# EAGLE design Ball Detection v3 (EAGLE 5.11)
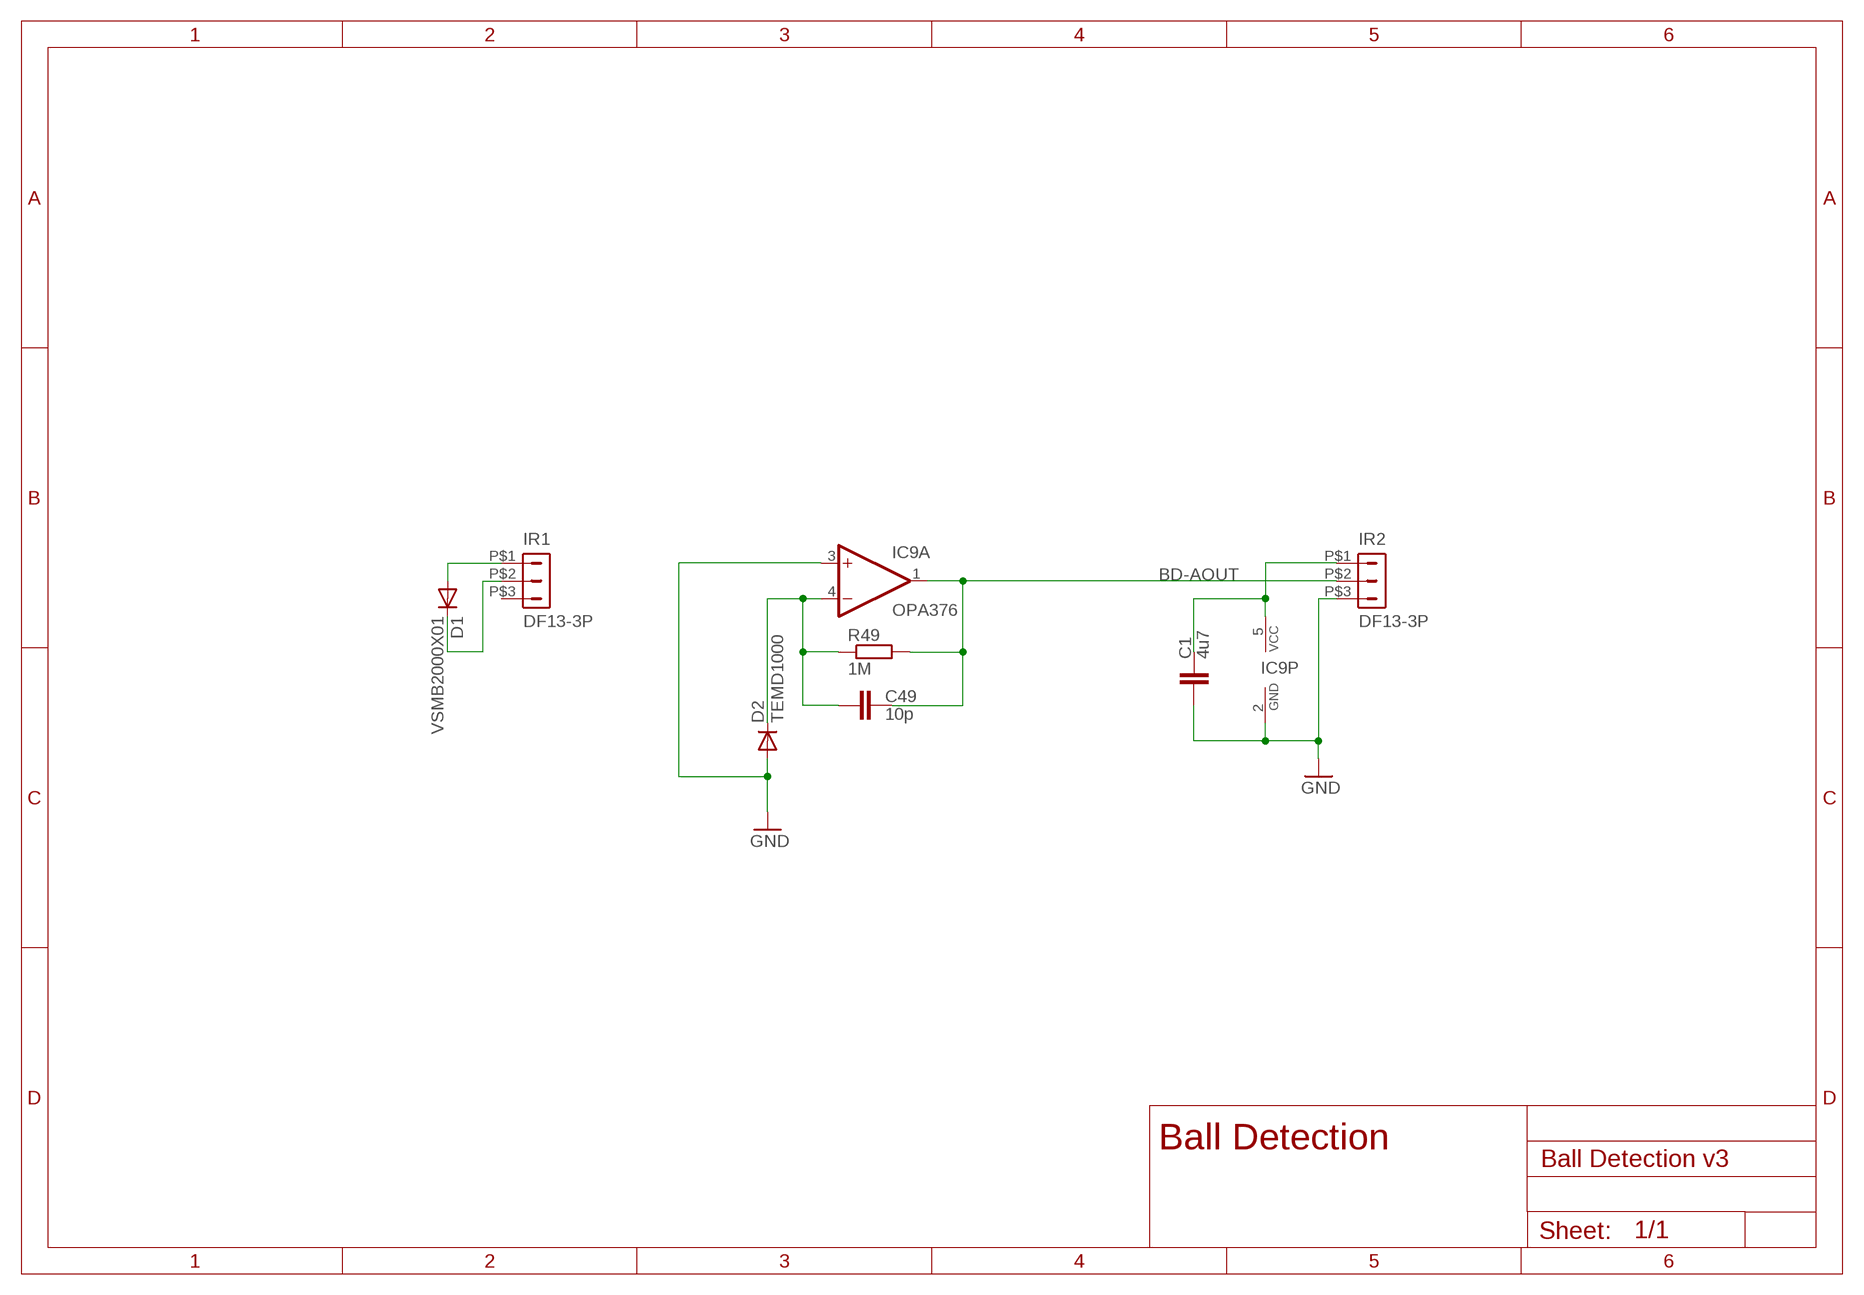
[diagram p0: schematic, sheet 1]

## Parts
C1  4u7  C-EUC0603  [C0603]
C49  10p  C-EUC0603  [C0603]
D1  VSMB2000X01  DIODE  [LED-GULLR]
D2  TEMD1000  DIODE  [LED-GULLR]
IC9  OPA376  AD-OP1RT  [SOT23-5]
IR1  DF13-3P  DF13-3P-1.25H  [DF13A-3P-1.25H]
IR2  DF13-3P  DF13-3P-1.25H  [DF13A-3P-1.25H]
R49  1M  R-EU_R0603  [R0603]

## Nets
BD-AOUT: C49.2 IC9.1(A:OUT) IR2.P$2 R49.2
GND: C1.1 D2.A IC9.2(P:GND) IC9.3(A:+IN) IR2.P$3
N$1: C1.2 IC9.5(P:VCC) IR2.P$1
N$114: C49.1 D2.C IC9.4(A:-IN) R49.1
N$182: D1.C IR1.P$2
VDD1: D1.A IR1.P$1
Unconnected: IR1.P$3

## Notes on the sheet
- Ball Detection

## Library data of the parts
C1 C49 = rcl:C-EU: CAPACITOR, European symbol
D1 D2 = Marvin:DIODE
IC9 = Marvin:AD-OP1
IR1 IR2 = con-hirose-df13:DF13-3P-1.25: DF13-3P 1.25mm Pitch Miniature Crimping Connector.
R49 = rcl:R-EU_: RESISTOR, European symbol

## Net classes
0 default: width 0.152 mm, clearance 0.152 mm

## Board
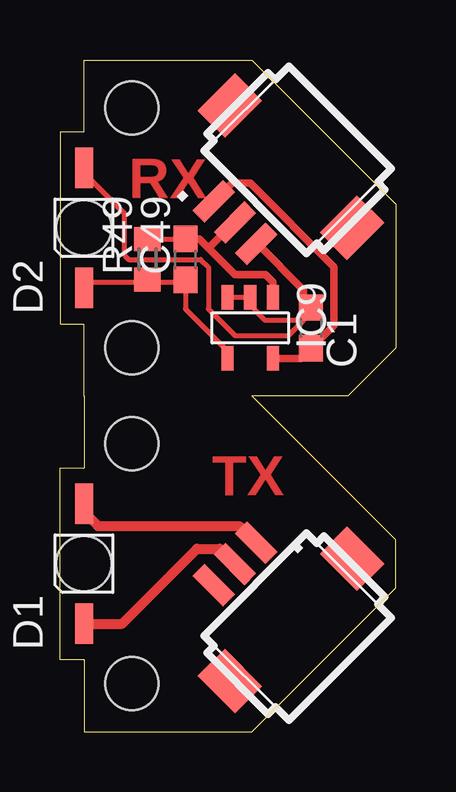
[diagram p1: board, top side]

Size 14 x 28 mm. Coordinates in mm from the lower left corner, seen from the top.
Outline: 1,0 8,0 14,6 14,8 8,14 12,14 14,16 14,22 8,28 1,28 1,25 0,25 0,17 1,17 1,14 1,11 0,11 0,3 1,3 1,0
Copper layers (1*16): Top 0.035mm / dielectric 1.5mm / Bottom 0.035mm
Design rules "PCB-POOL Standard": minimum track width 0.15mm, minimum drill 0.3mm, track to track 0.15mm, track to pad 0.15mm, pad to pad 0.15mm, via to via 0.15mm, smd to smd 0.15mm, copper to edge 0.3mm, drill to drill 0.2mm, minimum pad ring 0.2mm, minimum via ring 0.15mm, stop-mask expansion 0.075mm, vias tented up to drill 0mil, thermal gap 0.2mm
Holes 2.2 mm at 3,2 3,12 3,26 3,16
tKeepout: area 1.1,14.1 to 4.9,17.9; area 1.1,24.1 to 4.9,27.9; area 1.1,10.1 to 4.9,13.9; area 1.1,0.1 to 4.9,3.9

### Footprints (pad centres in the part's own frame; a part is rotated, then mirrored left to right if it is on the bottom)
C0603 = smd 1.1 x 1: 1 -0.85,0; 2 0.85,0
LED-GULLR = smd 1.7 x 0.75: A 2.5,0; C -2.5,0 | hole 2.3: 0,0
SOT23-5 = smd 1.016 x 0.508: 1 -1.27,0.953; 2 -1.27,0; 3 -1.27,-0.953; 4 1.27,-0.953; 5 1.27,0.953
DF13A-3P-1.25H = smd 1.6 x 2.2: M$0 -3.6,2.4; M$1 3.6,2.4 | smd 0.7 x 1.8: P$1 -1.25,-0.9; P$2 0,-0.9; P$3 1.25,-0.9
R0603 = smd 1 x 1.1: 1 -0.85,0; 2 0.85,0

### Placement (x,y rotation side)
C1  10.48,16.83 270 top
C49  5.24,19.68 90 top
D1  1,7 90 top
D2  1,21 90 top
IC9  7.94,16.83 270 top
IR1  7.94,6.35 225 top
IR2  7.94,21.86 315 top
R49  3.65,19.68 90 top

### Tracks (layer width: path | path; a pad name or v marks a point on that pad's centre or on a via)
BD-AOUT
  Top 0.203: R49.2 C49.2 | 7.25,21.22 IR2.P$2
  Top 0.305: IC9.1 8.89,18.73 8.57,19.05 7.3,19.05 6.19,20.16 | C49.2 5.82,20.54 6.19,20.16 | 6.19,20.16 7.25,21.22
GND
  Top 0.203: 10,17.3 9.84,17.14 8.57,17.14 7.94,17.78 IC9.2 IC9.3 | 10,17.3 10.38,17.68 | 10.16,17.14 9.53,16.51 7.3,16.51 6.19,17.62 6.19,19.37 5.87,19.68 2.86,19.68 2.7,19.84 2.7,21.59 1,23.29 D2.A | 10.16,17.14 | 10.16,17.14 10,17.3 | 8.24,20.34 IR2.P$3 | C1.1 10.16,18
  Top 0.305: 10.38,17.68 C1.1 | 8.24,20.34 10.16,18.41 10.16,18
N$1
  Top 0.305: IC9.5 10.06,15.56 C1.2 11.43,16.93 11.43,19.37 7.94,22.86 7.17,22.86 IR2.P$1
N$114
  Top 0.203: D2.C 0.91,18.68 0.95,18.73 3.07,18.73 R49.1 3.28,18.73 4.98,18.73 C49.1 5.24,17.62 6.99,15.88 IC9.4
N$182
  Top 0.406: D1.C 2.6,4.5 5.71,7.62 6.67,7.62 IR1.P$2
VDD1
  Top 0.406: D1.A 1,9.16 1.59,8.57 7.48,8.57 IR1.P$1

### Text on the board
Top: RX | TX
